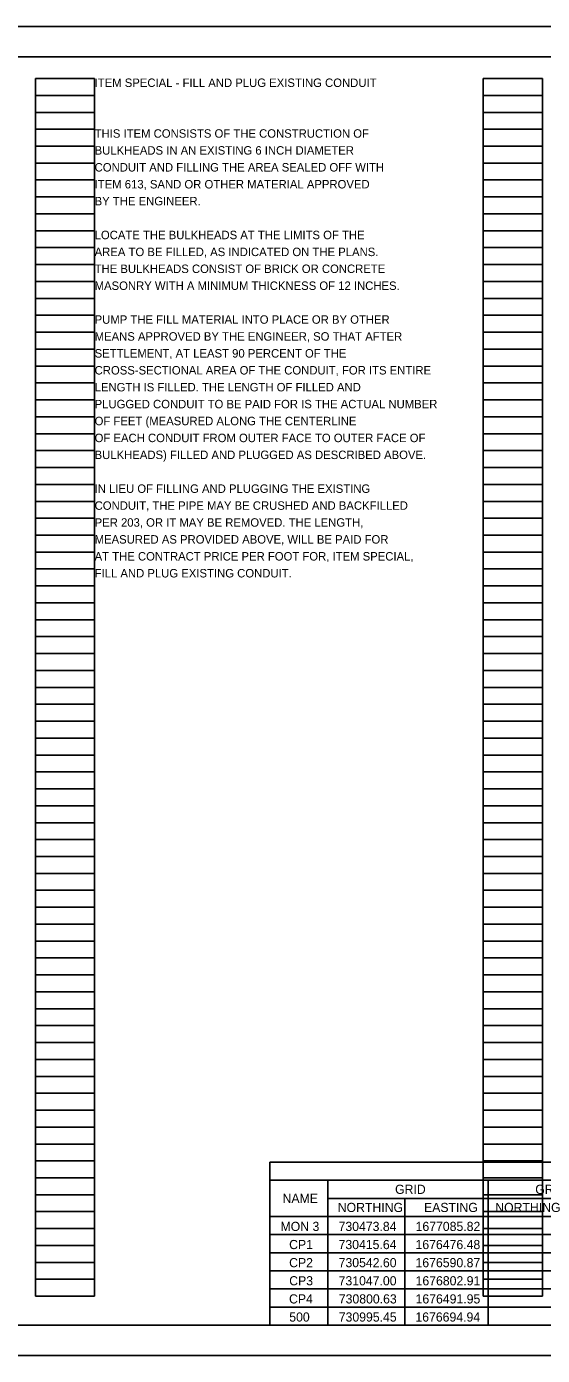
# Model space of a CAD drawing. Extents: x -15.9 to 34, y 0 to 22.
# Drawn here: x 8.69 to 17.24, y 0 to 22 of the extents above; entities that cross this region are included whole.
import ezdxf

# ---------------------------------------------------------------- set-up
doc = ezdxf.new("R2010")
doc.units = 0
for name, color, linetype in [('SH_Border', 7, 'Continuous'), ('SH_Cut_Line', 7, 'Continuous'), ('SH_Data', 7, 'Continuous'), ('SH_Text', 7, 'Continuous')]:
    doc.layers.add(name, color=color, linetype=linetype)

msp = doc.modelspace()

# ---------------------------------------------------------------- linework, layer by layer
at = {"layer": 'SH_Border'}
msp.add_lwpolyline([(1.5, 21.5), (33.5, 21.5), (33.5, 0.5), (1.5, 0.5)], close=True, dxfattribs=at)
at = {"layer": 'SH_Cut_Line'}
msp.add_lwpolyline([(0, 0), (34, 0), (34, 22), (0, 22)], close=True, dxfattribs=at)
at = {"layer": 'SH_Data'}
for p, q in [((8.84, 0.98), (8.84, 21.14)), ((8.84, 21.14), (9.82, 21.14)), ((9.82, 0.98), (9.82, 21.14)), ((16.26, 0.98), (16.26, 21.14)), ((16.26, 21.14), (17.24, 21.14)), ((17.24, 0.98), (17.24, 21.14)), ((8.84, 20.86), (9.82, 20.86)), ((16.26, 20.86), (17.24, 20.86)), ((8.84, 20.58), (9.82, 20.58)), ((16.26, 20.58), (17.24, 20.58)), ((8.84, 20.3), (9.82, 20.3)), ((16.26, 20.3), (17.24, 20.3)), ((8.84, 20.02), (9.82, 20.02)), ((16.26, 20.02), (17.24, 20.02)), ((8.84, 19.74), (9.82, 19.74)), ((16.26, 19.74), (17.24, 19.74)), ((8.84, 19.46), (9.82, 19.46)), ((16.26, 19.46), (17.24, 19.46)), ((8.84, 19.18), (9.82, 19.18)), ((16.26, 19.18), (17.24, 19.18)), ((8.84, 18.9), (9.82, 18.9)), ((16.26, 18.9), (17.24, 18.9)), ((8.84, 18.62), (9.82, 18.62)), ((16.26, 18.62), (17.24, 18.62)), ((8.84, 18.34), (9.82, 18.34)), ((16.26, 18.34), (17.24, 18.34)), ((8.84, 18.06), (9.82, 18.06)), ((16.26, 18.06), (17.24, 18.06)), ((8.84, 17.78), (9.82, 17.78)), ((16.26, 17.78), (17.24, 17.78)), ((8.84, 17.5), (9.82, 17.5)), ((16.26, 17.5), (17.24, 17.5)), ((8.84, 17.22), (9.82, 17.22)), ((16.26, 17.22), (17.24, 17.22)), ((8.84, 16.94), (9.82, 16.94)), ((16.26, 16.94), (17.24, 16.94)), ((8.84, 16.66), (9.82, 16.66)), ((16.26, 16.66), (17.24, 16.66)), ((8.84, 16.38), (9.82, 16.38)), ((16.26, 16.38), (17.24, 16.38)), ((8.84, 16.1), (9.82, 16.1)), ((16.26, 16.1), (17.24, 16.1)), ((8.84, 15.82), (9.82, 15.82)), ((16.26, 15.82), (17.24, 15.82)), ((8.84, 15.54), (9.82, 15.54)), ((16.26, 15.54), (17.24, 15.54)), ((8.84, 15.26), (9.82, 15.26)), ((16.26, 15.26), (17.24, 15.26)), ((8.84, 14.98), (9.82, 14.98)), ((16.26, 14.98), (17.24, 14.98)), ((8.84, 14.7), (9.82, 14.7)), ((16.26, 14.7), (17.24, 14.7)), ((8.84, 14.42), (9.82, 14.42)), ((16.26, 14.42), (17.24, 14.42)), ((8.84, 14.14), (9.82, 14.14)), ((16.26, 14.14), (17.24, 14.14)), ((8.84, 13.86), (9.82, 13.86)), ((16.26, 13.86), (17.24, 13.86)), ((8.84, 13.58), (9.82, 13.58)), ((16.26, 13.58), (17.24, 13.58)), ((8.84, 13.3), (9.82, 13.3)), ((16.26, 13.3), (17.24, 13.3)), ((8.84, 13.02), (9.82, 13.02)), ((16.26, 13.02), (17.24, 13.02)), ((8.84, 12.74), (9.82, 12.74)), ((16.26, 12.74), (17.24, 12.74)), ((8.84, 12.46), (9.82, 12.46)), ((16.26, 12.46), (17.24, 12.46)), ((8.84, 12.18), (9.82, 12.18)), ((16.26, 12.18), (17.24, 12.18)), ((8.84, 11.9), (9.82, 11.9)), ((16.26, 11.9), (17.24, 11.9)), ((8.84, 11.62), (9.82, 11.62)), ((16.26, 11.62), (17.24, 11.62)), ((8.84, 11.34), (9.82, 11.34)), ((16.26, 11.34), (17.24, 11.34)), ((8.84, 11.06), (9.82, 11.06)), ((16.26, 11.06), (17.24, 11.06)), ((8.84, 10.78), (9.82, 10.78)), ((16.26, 10.78), (17.24, 10.78)), ((8.84, 10.5), (9.82, 10.5)), ((16.26, 10.5), (17.24, 10.5)), ((8.84, 10.22), (9.82, 10.22)), ((16.26, 10.22), (17.24, 10.22)), ((8.84, 9.94), (9.82, 9.94)), ((16.26, 9.94), (17.24, 9.94)), ((8.84, 9.66), (9.82, 9.66)), ((16.26, 9.66), (17.24, 9.66)), ((8.84, 9.38), (9.82, 9.38)), ((16.26, 9.38), (17.24, 9.38)), ((8.84, 9.1), (9.82, 9.1)), ((16.26, 9.1), (17.24, 9.1)), ((8.84, 8.82), (9.82, 8.82)), ((16.26, 8.82), (17.24, 8.82)), ((8.84, 8.54), (9.82, 8.54)), ((16.26, 8.54), (17.24, 8.54)), ((8.84, 8.26), (9.82, 8.26)), ((16.26, 8.26), (17.24, 8.26)), ((8.84, 7.98), (9.82, 7.98)), ((16.26, 7.98), (17.24, 7.98)), ((8.84, 7.7), (9.82, 7.7)), ((16.26, 7.7), (17.24, 7.7)), ((8.84, 7.42), (9.82, 7.42)), ((16.26, 7.42), (17.24, 7.42)), ((8.84, 7.14), (9.82, 7.14)), ((16.26, 7.14), (17.24, 7.14)), ((8.84, 6.86), (9.82, 6.86)), ((16.26, 6.86), (17.24, 6.86)), ((8.84, 6.58), (9.82, 6.58)), ((16.26, 6.58), (17.24, 6.58)), ((8.84, 6.3), (9.82, 6.3)), ((16.26, 6.3), (17.24, 6.3)), ((8.84, 6.02), (9.82, 6.02)), ((16.26, 6.02), (17.24, 6.02)), ((8.84, 5.74), (9.82, 5.74)), ((16.26, 5.74), (17.24, 5.74)), ((8.84, 5.46), (9.82, 5.46)), ((16.26, 5.46), (17.24, 5.46)), ((8.84, 5.18), (9.82, 5.18)), ((16.26, 5.18), (17.24, 5.18)), ((8.84, 4.9), (9.82, 4.9)), ((16.26, 4.9), (17.24, 4.9)), ((8.84, 4.62), (9.82, 4.62)), ((16.26, 4.62), (17.24, 4.62)), ((8.84, 4.34), (9.82, 4.34)), ((16.26, 4.34), (17.24, 4.34)), ((8.84, 4.06), (9.82, 4.06)), ((16.26, 4.06), (17.24, 4.06)), ((8.84, 3.78), (9.82, 3.78)), ((16.26, 3.78), (17.24, 3.78)), ((8.84, 3.5), (9.82, 3.5)), ((16.26, 3.5), (17.24, 3.5)), ((8.84, 3.22), (9.82, 3.22)), ((16.26, 3.22), (17.24, 3.22)), ((8.84, 2.94), (9.82, 2.94)), ((16.26, 2.94), (17.24, 2.94)), ((8.84, 2.66), (9.82, 2.66)), ((16.26, 2.66), (17.24, 2.66)), ((8.84, 2.38), (9.82, 2.38)), ((16.26, 2.38), (17.24, 2.38)), ((8.84, 2.1), (9.82, 2.1)), ((16.26, 2.1), (17.24, 2.1)), ((8.84, 1.82), (9.82, 1.82)), ((16.26, 1.82), (17.24, 1.82)), ((8.84, 1.54), (9.82, 1.54)), ((16.26, 1.54), (17.24, 1.54)), ((8.84, 1.26), (9.82, 1.26)), ((16.26, 1.26), (17.24, 1.26)), ((8.84, 0.98), (9.82, 0.98)), ((16.26, 0.98), (17.24, 0.98))]:
    msp.add_line(p, q, dxfattribs=at)
at = {"layer": 'SH_Text'}
for p, q in [((12.725, 3.2), (32, 3.2)), ((12.725, 3.2), (12.725, 0.5)), ((12.725, 2.9), (32, 2.9)), ((13.685, 2.9), (13.685, 0.5)), ((16.34, 2.9), (16.34, 0.5)), ((13.685, 2.6), (18.695, 2.6)), ((14.96, 2.6), (14.96, 0.5)), ((12.725, 2.3), (32, 2.3)), ((12.725, 2), (32, 2)), ((12.725, 1.7), (32, 1.7)), ((12.725, 1.4), (32, 1.4)), ((12.725, 1.1), (32, 1.1)), ((12.725, 0.8), (32, 0.8)), ((12.725, 0.5), (32, 0.5))]:
    msp.add_line(p, q, dxfattribs=at)

# ---------------------------------------------------------------- texts
for s, height, p in [('ITEM SPECIAL - FILL AND PLUG EXISTING CONDUIT', 0.14, (9.82, 21)), ('THIS ITEM CONSISTS OF THE CONSTRUCTION OF', 0.14, (9.82, 20.16)), ('BULKHEADS IN AN EXISTING 6 INCH DIAMETER', 0.14, (9.82, 19.88)), ('CONDUIT AND FILLING THE AREA SEALED OFF WITH', 0.14, (9.82, 19.6)), ('ITEM 613, SAND OR OTHER MATERIAL APPROVED', 0.14, (9.82, 19.32)), ('BY THE ENGINEER.', 0.14, (9.82, 19.04)), ('LOCATE THE BULKHEADS AT THE LIMITS OF THE', 0.14, (9.82, 18.48)), ('AREA TO BE FILLED, AS INDICATED ON THE PLANS.', 0.14, (9.82, 18.2)), ('THE BULKHEADS CONSIST OF BRICK OR CONCRETE', 0.14, (9.82, 17.92)), ('MASONRY WITH A MINIMUM THICKNESS OF 12 INCHES.', 0.14, (9.82, 17.64)), ('PUMP THE FILL MATERIAL INTO PLACE OR BY OTHER', 0.14, (9.82, 17.08)), ('MEANS APPROVED BY THE ENGINEER, SO THAT AFTER', 0.14, (9.82, 16.8)), ('SETTLEMENT, AT LEAST 90 PERCENT OF THE', 0.14, (9.82, 16.52)), ('CROSS-SECTIONAL AREA OF THE CONDUIT, FOR ITS ENTIRE', 0.14, (9.82, 16.24)), ('LENGTH IS FILLED. THE LENGTH OF FILLED AND', 0.14, (9.82, 15.96)), ('PLUGGED CONDUIT TO BE PAID FOR IS THE ACTUAL NUMBER', 0.14, (9.82, 15.68)), ('OF FEET (MEASURED ALONG THE CENTERLINE', 0.14, (9.82, 15.4)), ('OF EACH CONDUIT FROM OUTER FACE TO OUTER FACE OF', 0.14, (9.82, 15.12)), ('BULKHEADS) FILLED AND PLUGGED AS DESCRIBED ABOVE.', 0.14, (9.82, 14.84)), ('IN LIEU OF FILLING AND PLUGGING THE EXISTING', 0.14, (9.82, 14.28)), ('CONDUIT, THE PIPE MAY BE CRUSHED AND BACKFILLED', 0.14, (9.82, 14)), ('PER 203, OR IT MAY BE REMOVED. THE LENGTH,', 0.14, (9.82, 13.72)), ('MEASURED AS PROVIDED ABOVE, WILL BE PAID FOR', 0.14, (9.82, 13.44)), ('AT THE CONTRACT PRICE PER FOOT FOR, ITEM SPECIAL,', 0.14, (9.82, 13.16)), ('FILL AND PLUG EXISTING CONDUIT.', 0.14, (9.82, 12.88)), ('NAME', 0.1518, (12.934, 2.524)), ('GRID', 0.1518, (14.798, 2.674)), ('GROUND', 0.1518, (17.121, 2.674)), ('NORTHING', 0.1518, (13.848, 2.374)), ('EASTING', 0.1518, (15.278, 2.374)), ('NORTHING', 0.1518, (16.458, 2.374)), ('MON 3', 0.1518, (12.9, 2.06)), ('730473.84', 0.1518, (13.862, 2.06)), ('1677085.82', 0.1518, (15.138, 2.06)), ('CP1', 0.1518, (13.043, 1.76)), ('730415.64', 0.1518, (13.862, 1.76)), ('1676476.48', 0.1518, (15.137, 1.76)), ('CP2', 0.1518, (13.043, 1.46)), ('730542.60', 0.1518, (13.863, 1.46)), ('1676590.87', 0.1518, (15.137, 1.46)), ('CP3', 0.1518, (13.044, 1.16)), ('731047.00', 0.1518, (13.863, 1.16)), ('1676802.91', 0.1518, (15.138, 1.16)), ('CP4', 0.1518, (13.041, 0.86)), ('730800.63', 0.1518, (13.866, 0.86)), ('1676491.95', 0.1518, (15.138, 0.86)), ('500', 0.1518, (13.045, 0.56)), ('730995.45', 0.1518, (13.865, 0.56)), ('1676694.94', 0.1518, (15.135, 0.56))]:
    msp.add_text(s, height=height, dxfattribs=at).set_placement(p)

doc.saveas('drawing.dxf')
